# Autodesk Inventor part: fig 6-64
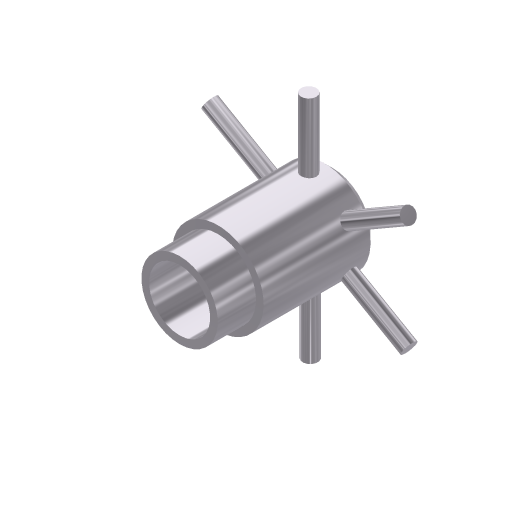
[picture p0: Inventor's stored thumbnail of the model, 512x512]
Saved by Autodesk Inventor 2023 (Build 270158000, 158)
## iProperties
Created: 2001-12
Part Number: fig 6-64
Document SubType Name: Modeling
Designer: Renu Muthoo
Density: 1 g/cm^3
Material: Generic
Appearance: Metal-AL-6061 (Polished)
Control State: 0
Master: False
Checked Out: False
Shininess: 77.0
Angle Display Precision: 2
Document Length Units: 11269
Document Angle Units: 11279
Document Time Units: 11290
Document Mass Units: 11283
Document Length Units Precision: 3
Document Angle Units Precision: 2
Compacted: True
Density: 0.0
Volumn: 0.0
Area: 0.0
PropertySet Name: Model Information
Author: Renu Muthoo
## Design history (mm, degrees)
sketch "Sketch2"
  geometry: L1 (-9.573, -4.327)-(-9.573, -5.327); L2 (-9.573, -5.327)-(-4.573, -5.327); L3 (-4.573, -5.327)-(-4.573, -6.327); L4 (-4.573, -6.327)-(9.427, -6.327); L5 (9.427, -6.327)-(10.427, -5.327); L6 (10.427, -5.327)-(10.427, -4.327); L7 (10.427, -4.327)-(-9.573, -4.327); L8 (-13.687, -0.327)-(14, -0.327)
  constraints: 16 end point, 5 parallel, 1 perpendicular, 1 vertical
  dimensions: "d9" = 20 distance of L6.end L1.start; "d10" = 5 distance of L1.end L2.end; "d11" = 12 diameter of L4 L8; "d12" = 10 diameter of L2 L8; "d13" = 8 diameter of L7 L8; "d14" = 45 deg angle of L5 L4; "d15" = 1 horizontal distance of L5.end L4.end
revolve "Revolution2" sketch "Sketch2" stored, may be unused: angle "d16" = 90 deg
workplane "Work Plane1"
workplane "Work Plane2"
sketch "Sketch3"
  geometry: L1 (-4, 8)-(4, 8) reference; C1 r 1 at (-0.098, 5)
  constraints: 1 centre point
  dimensions: "d18" = 3 distance from line of L1 C1.centre; "d19" = 2 diameter of C1
extrude "Extrusion1" join sketch "Sketch3" distance "d20" = 10; taper "d21" = 0 deg
pattern_circular "Circular Pattern3" dims angle "d29" = 360 deg
body "Solid1"
other parameters: "d17" = -1
